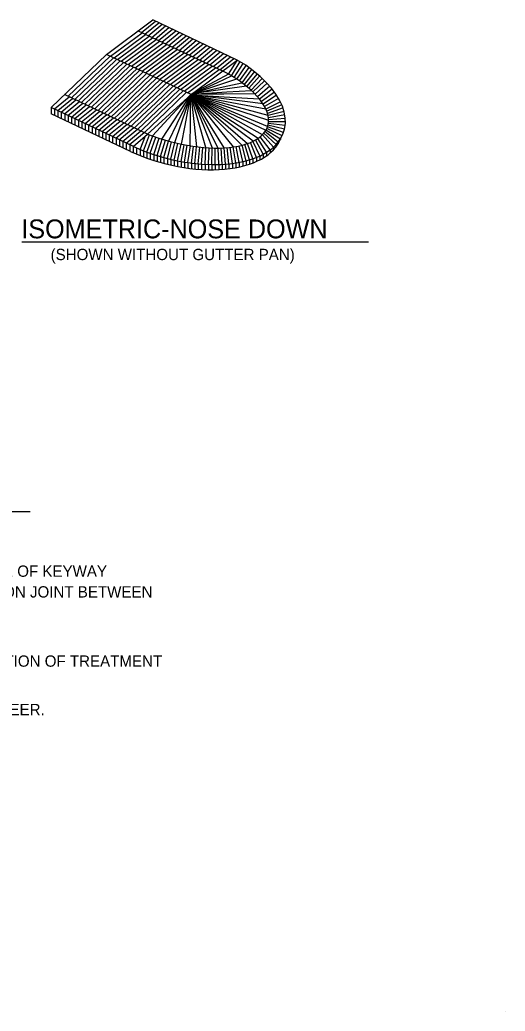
# Model space of a CAD drawing. Extents: x -28.1 to -20.9, y 67 to 77.1.
# Drawn here: x -23.48 to -20.9, y 66.96 to 72.22 of the extents above; entities that cross this region are included whole.
import ezdxf

# ---------------------------------------------------------------- set-up
doc = ezdxf.new("R2010")
doc.units = 0
for name, color, linetype in [('DETL-LINE', 7, 'Continuous'), ('DETL-NOTE', 7, 'Continuous'), ('DETL-PATT', 7, 'Continuous'), ('DETL-TITL', 7, 'Continuous'), ('TTLB-TEXT', 7, 'Continuous')]:
    doc.layers.add(name, color=color, linetype=linetype)

msp = doc.modelspace()

# ---------------------------------------------------------------- linework, layer by layer
at = {"layer": 'DETL-LINE'}
for p, q in [((-23.0204, 72.0386), (-22.7745, 72.2219)), ((-22.3251, 72.0086), (-22.7745, 72.2219)), ((-22.3989, 71.9477), (-22.8531, 72.1633)), ((-23.3147, 71.7573), (-23.0204, 72.0386)), ((-22.5711, 71.8253), (-23.0204, 72.0386)), ((-22.5711, 71.8253), (-22.3251, 72.0086)), ((-22.8013, 71.6157), (-23.2433, 71.8255)), ((-22.5711, 71.8253), (-22.8013, 71.6157)), ((-22.2288, 71.8274), (-22.2295, 71.8267)), ((-22.8798, 71.5508), (-23.3147, 71.7573)), ((-23.3147, 71.7573), (-23.3147, 71.7238)), ((-22.8928, 71.5235), (-23.3147, 71.7238)), ((-22.1594, 71.6913), (-22.1594, 71.6913)), ((-22.8783, 71.5502), (-22.8013, 71.6157)), ((-22.0965, 71.5888), (-22.0965, 71.586))]:
    msp.add_line(p, q, dxfattribs=at)
for centre, major_axis, ratio, start_param, end_param in [((-22.6485, 71.8037), (0.5717, -0.1716), 0.533929, 4.460318, 7.420458), ((-22.6485, 71.8037), (0.4847, -0.1455), 0.450197, 0.227567, 1.169614), ((-22.6485, 71.8037), (0.4847, -0.1455), 0.450197, 4.528972, 6.510752), ((-22.6615, 71.7763), (0.5717, -0.1716), 0.533929, 4.460318, 6.249007)]:
    msp.add_ellipse(centre, major_axis=major_axis, ratio=ratio, start_param=start_param, end_param=end_param, dxfattribs=at)
at = {"layer": 'DETL-PATT'}
for p, q in [((-22.8343, 72.1544), (-22.7605, 72.2153)), ((-22.8161, 72.1458), (-22.7424, 72.2067)), ((-22.798, 72.1372), (-22.7242, 72.1981)), ((-22.9985, 72.0282), (-22.8312, 72.1529)), ((-22.9799, 72.0194), (-22.8126, 72.1441)), ((-22.7799, 72.1286), (-22.7061, 72.1894)), ((-22.7617, 72.12), (-22.688, 72.1808)), ((-22.7436, 72.1114), (-22.6698, 72.1722)), ((-22.7255, 72.1028), (-22.6517, 72.1636)), ((-22.7073, 72.0941), (-22.6336, 72.155)), ((-22.6892, 72.0855), (-22.6154, 72.1464)), ((-22.9613, 72.0105), (-22.794, 72.1353)), ((-22.9427, 72.0017), (-22.7754, 72.1265)), ((-22.9242, 71.9929), (-22.7568, 72.1177)), ((-22.9056, 71.9841), (-22.7383, 72.1088)), ((-22.887, 71.9753), (-22.7197, 72.1)), ((-22.8684, 71.9664), (-22.7011, 72.0912)), ((-22.6711, 72.0769), (-22.5973, 72.1378)), ((-22.6529, 72.0683), (-22.5792, 72.1292)), ((-22.6348, 72.0597), (-22.561, 72.1206)), ((-22.6167, 72.0511), (-22.5429, 72.112)), ((-22.5985, 72.0425), (-22.5248, 72.1034)), ((-22.5804, 72.0339), (-22.5066, 72.0948)), ((-22.8498, 71.9576), (-22.6825, 72.0824)), ((-22.8312, 71.9488), (-22.6639, 72.0735)), ((-22.7941, 71.9312), (-22.6267, 72.0559)), ((-22.7755, 71.9223), (-22.6082, 72.0471)), ((-22.7569, 71.9135), (-22.5896, 72.0382)), ((-22.7005, 72.0235), (-22.6453, 72.0647)), ((-22.5623, 72.0253), (-22.4885, 72.0862)), ((-22.5441, 72.0167), (-22.4704, 72.0775)), ((-22.526, 72.008), (-22.4522, 72.0689)), ((-22.5079, 71.9994), (-22.4341, 72.0603)), ((-22.4897, 71.9908), (-22.416, 72.0517)), ((-22.4716, 71.9822), (-22.3978, 72.0431)), ((-23.1048, 71.9291), (-23.0003, 72.029)), ((-23.0864, 71.9216), (-22.9827, 72.0207)), ((-23.0789, 71.9037), (-22.9651, 72.0124)), ((-23.0505, 71.9056), (-22.9476, 72.004)), ((-23.0343, 71.896), (-22.93, 71.9957)), ((-22.9977, 71.9057), (-22.9124, 71.9873)), ((-22.8127, 71.94), (-22.701, 72.0232)), ((-22.7383, 71.9047), (-22.571, 72.0294)), ((-22.7197, 71.8959), (-22.5524, 72.0206)), ((-22.7011, 71.887), (-22.5338, 72.0118)), ((-22.6826, 71.8782), (-22.5152, 72.0029)), ((-22.664, 71.8694), (-22.4967, 71.9941)), ((-22.6454, 71.8606), (-22.4781, 71.9853)), ((-22.4535, 71.9736), (-22.3797, 72.0345)), ((-22.4353, 71.965), (-22.3616, 72.0259)), ((-22.4172, 71.9564), (-22.3434, 72.0173)), ((-22.3285, 72.0061), (-22.3731, 71.9337)), ((-22.3109, 72), (-22.3573, 71.9246)), ((-22.295, 71.99), (-22.3429, 71.9159)), ((-22.9936, 71.8846), (-22.8948, 71.979)), ((-22.9628, 71.8888), (-22.8772, 71.9706)), ((-22.9625, 71.864), (-22.8596, 71.9623)), ((-22.9349, 71.84), (-22.8245, 71.9456)), ((-22.9324, 71.8675), (-22.8421, 71.9539)), ((-22.9089, 71.8397), (-22.8069, 71.9372)), ((-22.6268, 71.8517), (-22.4595, 71.9765)), ((-22.6082, 71.8429), (-22.4409, 71.9677)), ((-22.5896, 71.8341), (-22.4223, 71.9588)), ((-22.3728, 71.9336), (-22.4448, 71.895)), ((-22.2794, 71.9797), (-22.3288, 71.9069)), ((-22.2642, 71.969), (-22.315, 71.8977)), ((-22.2493, 71.9582), (-22.3016, 71.8883)), ((-22.2347, 71.9469), (-22.2886, 71.8787)), ((-22.2204, 71.9354), (-22.2759, 71.8688)), ((-23.2232, 71.816), (-23.1527, 71.8833)), ((-23.1527, 71.8833), (-23.1048, 71.9291)), ((-23.1431, 71.8423), (-23.0789, 71.9037)), ((-23.1344, 71.8757), (-23.0864, 71.9216)), ((-23.1043, 71.829), (-23.0343, 71.896)), ((-23.0979, 71.8603), (-23.0505, 71.9056)), ((-23.0654, 71.8159), (-22.9936, 71.8846)), ((-23.0612, 71.845), (-22.9977, 71.9057)), ((-23.0246, 71.8298), (-22.9628, 71.8888)), ((-22.9073, 71.8162), (-22.7893, 71.9289)), ((-22.8838, 71.8134), (-22.7717, 71.9205)), ((-22.8794, 71.7924), (-22.7542, 71.9122)), ((-22.8655, 71.7806), (-22.7366, 71.9038)), ((-22.8469, 71.7733), (-22.719, 71.8955)), ((-22.8066, 71.7866), (-22.7014, 71.8872)), ((-22.8053, 71.7627), (-22.6838, 71.8788)), ((-22.5637, 71.8293), (-22.4306, 71.8899)), ((-22.4141, 71.8794), (-22.5637, 71.8293)), ((-22.4448, 71.895), (-22.5605, 71.8332)), ((-22.4306, 71.8899), (-22.3561, 71.9239)), ((-22.3299, 71.9076), (-22.4141, 71.8794)), ((-22.3999, 71.8662), (-22.3014, 71.8882)), ((-22.2065, 71.9235), (-22.2636, 71.8586)), ((-22.193, 71.9113), (-22.2517, 71.8483)), ((-22.1799, 71.8987), (-22.2424, 71.8396)), ((-22.1672, 71.8856), (-22.2295, 71.8267)), ((-23.2056, 71.8076), (-23.1344, 71.8757)), ((-23.1881, 71.7993), (-23.1431, 71.8423)), ((-23.1705, 71.7909), (-23.0979, 71.8603)), ((-23.1529, 71.7826), (-23.1043, 71.829)), ((-23.1353, 71.7743), (-23.0612, 71.845)), ((-23.1001, 71.7575), (-23.0246, 71.8298)), ((-23.0266, 71.8027), (-22.9625, 71.864)), ((-22.989, 71.8135), (-22.9324, 71.8675)), ((-22.9883, 71.789), (-22.9349, 71.84)), ((-22.9553, 71.7954), (-22.9089, 71.8397)), ((-22.8013, 71.6157), (-22.5711, 71.8253)), ((-22.7633, 71.7526), (-22.6487, 71.8621)), ((-22.7586, 71.7822), (-22.6662, 71.8705)), ((-22.7306, 71.7335), (-22.6135, 71.8454)), ((-22.7216, 71.7672), (-22.6311, 71.8538)), ((-22.7053, 71.7325), (-22.5959, 71.8371)), ((-22.5698, 71.8252), (-22.6463, 71.669)), ((-22.6211, 71.6755), (-22.5698, 71.8252)), ((-22.3939, 71.7253), (-22.5715, 71.8249)), ((-22.5713, 71.825), (-22.3978, 71.7428)), ((-22.5061, 71.6977), (-22.5711, 71.8253)), ((-22.5708, 71.8255), (-22.417, 71.7253)), ((-22.4265, 71.7166), (-22.5708, 71.8254)), ((-22.4672, 71.6597), (-22.5705, 71.8257)), ((-22.5704, 71.8257), (-22.4707, 71.7015)), ((-22.3963, 71.8278), (-22.5683, 71.8273)), ((-22.5677, 71.8278), (-22.38, 71.8391)), ((-22.39, 71.8537), (-22.5663, 71.8288)), ((-22.5658, 71.8292), (-22.3999, 71.8662)), ((-22.231, 71.8283), (-22.3963, 71.8278)), ((-22.277, 71.8697), (-22.39, 71.8537)), ((-22.38, 71.8391), (-22.2503, 71.847)), ((-22.1531, 71.8701), (-22.2176, 71.8139)), ((-22.1397, 71.8541), (-22.2066, 71.8008)), ((-22.1274, 71.8379), (-22.1966, 71.7877)), ((-23.297, 71.7489), (-23.2185, 71.8137)), ((-23.2789, 71.7403), (-23.2003, 71.8051)), ((-23.2608, 71.7317), (-23.1822, 71.7965)), ((-23.2426, 71.7231), (-23.1641, 71.7879)), ((-23.2245, 71.7145), (-23.1459, 71.7793)), ((-23.1177, 71.7659), (-23.0654, 71.8159)), ((-23.0826, 71.7492), (-23.0266, 71.8027)), ((-23.065, 71.7409), (-22.989, 71.8135)), ((-23.0474, 71.7325), (-22.9883, 71.789)), ((-23.0298, 71.7242), (-22.9553, 71.7954)), ((-22.9545, 71.771), (-22.9073, 71.8162)), ((-22.9376, 71.762), (-22.8838, 71.8134)), ((-22.9091, 71.7641), (-22.8794, 71.7924)), ((-22.9055, 71.7424), (-22.8655, 71.7806)), ((-22.8884, 71.7335), (-22.8469, 71.7733)), ((-22.8627, 71.733), (-22.8066, 71.7866)), ((-22.8318, 71.7122), (-22.7586, 71.7822)), ((-22.5768, 71.8201), (-22.6929, 71.6957)), ((-22.6594, 71.6909), (-22.5739, 71.8227)), ((-22.5738, 71.8228), (-22.6045, 71.6611)), ((-22.574, 71.6806), (-22.5729, 71.8235)), ((-22.5727, 71.8238), (-22.5546, 71.6665)), ((-22.5338, 71.6882), (-22.5723, 71.8241)), ((-22.5709, 71.8242), (-22.5123, 71.6764)), ((-22.4355, 71.6898), (-22.5709, 71.8242)), ((-22.5709, 71.8242), (-22.4249, 71.6975)), ((-22.377, 71.7441), (-22.5709, 71.8242)), ((-22.5709, 71.8242), (-22.3721, 71.7589)), ((-22.3833, 71.8005), (-22.5709, 71.8242)), ((-22.5709, 71.8242), (-22.3648, 71.8114)), ((-22.385, 71.7739), (-22.5688, 71.8232)), ((-22.5688, 71.8232), (-22.355, 71.7832)), ((-22.1621, 71.7142), (-22.385, 71.7739)), ((-22.1886, 71.7759), (-22.3833, 71.8005)), ((-22.3648, 71.8114), (-22.2073, 71.8017)), ((-22.355, 71.7832), (-22.174, 71.7493)), ((-22.1161, 71.8214), (-22.1879, 71.7747)), ((-22.1059, 71.8048), (-22.1803, 71.7618)), ((-22.0963, 71.787), (-22.1736, 71.7485)), ((-23.2965, 71.7487), (-23.2965, 71.7152)), ((-23.2783, 71.7401), (-23.2783, 71.7065)), ((-23.2602, 71.7314), (-23.2602, 71.6979)), ((-23.242, 71.7228), (-23.242, 71.6893)), ((-23.2063, 71.7059), (-23.1278, 71.7707)), ((-23.1882, 71.6973), (-23.1097, 71.7621)), ((-23.1701, 71.6887), (-23.0916, 71.7535)), ((-23.1519, 71.68), (-23.0734, 71.7449)), ((-23.1338, 71.6714), (-23.0553, 71.7363)), ((-23.1157, 71.6628), (-23.0372, 71.7277)), ((-23.0122, 71.7158), (-22.9545, 71.771)), ((-22.9947, 71.7075), (-22.9376, 71.762)), ((-22.9771, 71.6991), (-22.9091, 71.7641)), ((-22.9595, 71.6908), (-22.9055, 71.7424)), ((-22.9419, 71.6824), (-22.8884, 71.7335)), ((-22.9243, 71.6741), (-22.8627, 71.733)), ((-22.8716, 71.649), (-22.7633, 71.7526)), ((-22.857, 71.7133), (-22.8053, 71.7627)), ((-22.854, 71.6407), (-22.7216, 71.7672)), ((-22.8364, 71.6324), (-22.7306, 71.7335)), ((-22.8188, 71.624), (-22.7053, 71.7325)), ((-22.417, 71.7253), (-22.2142, 71.5932)), ((-22.3978, 71.7428), (-22.1731, 71.6365)), ((-22.1918, 71.612), (-22.3939, 71.7253)), ((-22.1644, 71.6563), (-22.377, 71.7441)), ((-22.3721, 71.7589), (-22.1594, 71.689)), ((-22.0888, 71.7708), (-22.1687, 71.7367)), ((-22.0824, 71.7544), (-22.1649, 71.7254)), ((-22.0768, 71.7362), (-22.162, 71.7134)), ((-23.2238, 71.7142), (-23.2238, 71.6806)), ((-23.2056, 71.7055), (-23.2056, 71.672)), ((-23.1874, 71.6969), (-23.1874, 71.6634)), ((-23.1693, 71.6883), (-23.1693, 71.6547)), ((-23.1511, 71.6796), (-23.1511, 71.6461)), ((-23.1329, 71.671), (-23.1329, 71.6375)), ((-23.0976, 71.6542), (-23.019, 71.719)), ((-23.0794, 71.6456), (-23.0009, 71.7104)), ((-23.0613, 71.637), (-22.9827, 71.7018)), ((-23.0432, 71.6284), (-22.9646, 71.6932)), ((-23.025, 71.6198), (-22.9465, 71.6846)), ((-23.0069, 71.6112), (-22.9283, 71.676)), ((-22.9888, 71.6026), (-22.9102, 71.6674)), ((-22.9067, 71.6657), (-22.857, 71.7133)), ((-22.8892, 71.6574), (-22.8318, 71.7122)), ((-22.6929, 71.6957), (-22.7765, 71.6063)), ((-22.7256, 71.589), (-22.6594, 71.6909)), ((-22.6463, 71.669), (-22.6904, 71.5787)), ((-22.6572, 71.57), (-22.6211, 71.6755)), ((-22.575, 71.5534), (-22.574, 71.6806)), ((-22.4928, 71.5436), (-22.5338, 71.6882)), ((-22.5123, 71.6764), (-22.459, 71.5418)), ((-22.4264, 71.5414), (-22.5061, 71.6977)), ((-22.4707, 71.7015), (-22.4509, 71.6769)), ((-22.4509, 71.6769), (-22.3468, 71.5472)), ((-22.3009, 71.5561), (-22.4355, 71.6898)), ((-22.2417, 71.5772), (-22.4265, 71.7166)), ((-22.4249, 71.6975), (-22.2718, 71.5648)), ((-22.0708, 71.6602), (-22.1608, 71.6714)), ((-22.0728, 71.7185), (-22.1602, 71.7025)), ((-22.0695, 71.6798), (-22.1597, 71.6811)), ((-22.0702, 71.6989), (-22.1594, 71.6913)), ((-23.1147, 71.6624), (-23.1147, 71.6288)), ((-23.0965, 71.6537), (-23.0965, 71.6202)), ((-23.0783, 71.6451), (-23.0783, 71.6116)), ((-23.0602, 71.6365), (-23.0602, 71.6029)), ((-23.042, 71.6278), (-23.042, 71.5943)), ((-23.0238, 71.6192), (-23.0238, 71.5857)), ((-22.9706, 71.594), (-22.8921, 71.6588)), ((-22.9525, 71.5854), (-22.8739, 71.6502)), ((-22.9343, 71.5768), (-22.8558, 71.6416)), ((-22.9162, 71.5681), (-22.8377, 71.6329)), ((-22.8981, 71.5595), (-22.8196, 71.6243)), ((-22.6045, 71.6611), (-22.6232, 71.5623)), ((-22.5546, 71.6665), (-22.5411, 71.5485)), ((-22.3943, 71.5425), (-22.4672, 71.6597)), ((-22.1196, 71.5593), (-22.1844, 71.6202)), ((-22.1079, 71.5728), (-22.1783, 71.6283)), ((-22.0965, 71.5888), (-22.1728, 71.6371)), ((-22.087, 71.6058), (-22.1684, 71.6457)), ((-22.0792, 71.6244), (-22.1649, 71.6546)), ((-22.0741, 71.6417), (-22.1626, 71.6627)), ((-23.0056, 71.6106), (-23.0056, 71.577)), ((-22.9874, 71.6019), (-22.9874, 71.5684)), ((-22.9693, 71.5933), (-22.9693, 71.5598)), ((-22.9511, 71.5847), (-22.9511, 71.5512)), ((-22.9329, 71.576), (-22.9329, 71.5425)), ((-22.9147, 71.5674), (-22.9147, 71.5339)), ((-22.842, 71.5345), (-22.8123, 71.6067)), ((-22.8238, 71.5272), (-22.7909, 71.6117)), ((-22.8056, 71.5203), (-22.7742, 71.6054)), ((-22.7874, 71.5138), (-22.7575, 71.5995)), ((-22.7693, 71.5076), (-22.7408, 71.5939)), ((-22.7511, 71.5018), (-22.7241, 71.5885)), ((-22.7329, 71.4963), (-22.7073, 71.5835)), ((-22.7147, 71.4911), (-22.6907, 71.5787)), ((-22.6965, 71.4863), (-22.674, 71.5743)), ((-22.6783, 71.4818), (-22.6573, 71.5701)), ((-22.6602, 71.4776), (-22.6406, 71.5661)), ((-22.642, 71.4738), (-22.624, 71.5625)), ((-22.242, 71.4846), (-22.2702, 71.5653)), ((-22.2238, 71.4914), (-22.2558, 71.5709)), ((-22.2056, 71.4993), (-22.2418, 71.5772)), ((-22.1874, 71.5084), (-22.2282, 71.5843)), ((-22.1693, 71.519), (-22.2153, 71.5924)), ((-22.1511, 71.5314), (-22.2032, 71.6015)), ((-22.1325, 71.5466), (-22.1917, 71.612)), ((-22.1087, 71.5719), (-22.1087, 71.5629)), ((-22.8965, 71.5588), (-22.8965, 71.5252)), ((-22.8783, 71.5502), (-22.8783, 71.517)), ((-22.8602, 71.5421), (-22.8602, 71.5092)), ((-22.842, 71.5345), (-22.842, 71.5019)), ((-22.8238, 71.5272), (-22.8238, 71.4949)), ((-22.8056, 71.5203), (-22.8056, 71.4882)), ((-22.7874, 71.5138), (-22.7874, 71.4819)), ((-22.6238, 71.4702), (-22.6074, 71.5591)), ((-22.6056, 71.467), (-22.5907, 71.556)), ((-22.5874, 71.4642), (-22.5742, 71.5532)), ((-22.5693, 71.4616), (-22.5576, 71.5507)), ((-22.5511, 71.4594), (-22.5411, 71.5485)), ((-22.5329, 71.4575), (-22.5246, 71.5465)), ((-22.5147, 71.456), (-22.5081, 71.5449)), ((-22.4965, 71.4548), (-22.4917, 71.5435)), ((-22.4783, 71.454), (-22.4753, 71.5425)), ((-22.4602, 71.4535), (-22.4589, 71.5418)), ((-22.442, 71.4535), (-22.4426, 71.5415)), ((-22.4238, 71.4538), (-22.4264, 71.5414)), ((-22.4057, 71.4546), (-22.4103, 71.5418)), ((-22.3876, 71.4557), (-22.3943, 71.5425)), ((-22.3693, 71.4574), (-22.3782, 71.5437)), ((-22.3511, 71.4595), (-22.3623, 71.5453)), ((-22.3329, 71.4622), (-22.3465, 71.5473)), ((-22.3147, 71.4653), (-22.3308, 71.5498)), ((-22.2965, 71.4691), (-22.3154, 71.5528)), ((-22.2783, 71.4735), (-22.3001, 71.5563)), ((-22.2602, 71.4787), (-22.285, 71.5605)), ((-22.1693, 71.519), (-22.1693, 71.5002)), ((-22.1511, 71.5314), (-22.1511, 71.5143)), ((-22.1329, 71.5462), (-22.1329, 71.5315)), ((-22.1208, 71.558), (-22.1208, 71.5456)), ((-22.7693, 71.5076), (-22.7693, 71.476)), ((-22.7511, 71.5018), (-22.7511, 71.4704)), ((-22.7329, 71.4963), (-22.7329, 71.4652)), ((-22.7147, 71.4911), (-22.7147, 71.4602)), ((-22.6965, 71.4863), (-22.6965, 71.4557)), ((-22.6783, 71.4818), (-22.6783, 71.4514)), ((-22.6602, 71.4776), (-22.6602, 71.4474)), ((-22.642, 71.4738), (-22.642, 71.4438)), ((-22.6238, 71.4702), (-22.6238, 71.4405)), ((-22.6056, 71.467), (-22.6056, 71.4375)), ((-22.5874, 71.4642), (-22.5874, 71.4349)), ((-22.5693, 71.4616), (-22.5693, 71.4326)), ((-22.5511, 71.4594), (-22.5511, 71.4306)), ((-22.5329, 71.4575), (-22.5329, 71.429)), ((-22.3693, 71.4574), (-22.3693, 71.4315)), ((-22.3511, 71.4595), (-22.3511, 71.434)), ((-22.3329, 71.4622), (-22.3329, 71.437)), ((-22.3147, 71.4653), (-22.3147, 71.4406)), ((-22.2965, 71.4691), (-22.2965, 71.4448)), ((-22.2783, 71.4735), (-22.2783, 71.4498)), ((-22.2602, 71.4787), (-22.2602, 71.4555)), ((-22.242, 71.4846), (-22.242, 71.462)), ((-22.2238, 71.4914), (-22.2238, 71.4696)), ((-22.2056, 71.4993), (-22.2056, 71.4783)), ((-22.1874, 71.5084), (-22.1874, 71.4884)), ((-22.5147, 71.456), (-22.5147, 71.4277)), ((-22.4965, 71.4548), (-22.4965, 71.4268)), ((-22.4783, 71.454), (-22.4783, 71.4263)), ((-22.4602, 71.4535), (-22.4602, 71.4261)), ((-22.442, 71.4535), (-22.442, 71.4261)), ((-22.4238, 71.4535), (-22.4238, 71.4261)), ((-22.4056, 71.4535), (-22.4056, 71.428)), ((-22.3874, 71.4535), (-22.3874, 71.4295))]:
    msp.add_line(p, q, dxfattribs=at)
at = {"layer": 'DETL-TITL'}
for p, q in [((-23.469, 71.0436), (-21.6276, 71.0436)), ((-26.9957, 69.6121), (-23.4256, 69.6121))]:
    msp.add_line(p, q, dxfattribs=at)
at = {"layer": 'TTLB-TEXT'}
msp.add_line((-20.9022, 66.96), (-20.9022, 66.96), dxfattribs=at)

# ---------------------------------------------------------------- texts
at = {"layer": 'DETL-NOTE'}
for s, p in [('(SHOWN WITHOUT GUTTER PAN)', (-23.3169, 70.9465)), ("1. UNLESS OTHERWISE SPECIFIED, LONGITUDINAL TIE BAR DEVICE, TYPE 'A' OR TYPE 'B', PLACED AT MIDDLE OF KEYWAY", (-27.831, 69.2656)), ('   & SPACED ACCORDING TO SPECIFICATIONS FOR CONCRETE PAVEMENT SHALL BE USED AT CONSTRUCTION JOINT BETWEEN', (-27.831, 69.1556)), ('2. JOINT SPACING WILL BE A MAXIMUM OF 10\'-0" APART, SEE SPECIFICATIONS FOR LOCATION AND DESCRIPTION OF TREATMENT', (-27.8323, 68.7883)), ('3. ALLOW 4" O HOLES IN MEDIAN FOR SIGNS, SPACED AS SHOWN ON PLANS OR AS DIRECTED BY THE ENGINEER.', (-27.8349, 68.531))]:
    msp.add_text(s, height=0.06, dxfattribs=at).set_placement(p)
at = {"layer": 'DETL-TITL'}
msp.add_text('ISOMETRIC-NOSE DOWN', height=0.1, dxfattribs=at).set_placement((-23.4726, 71.0622))

doc.saveas('drawing.dxf')
